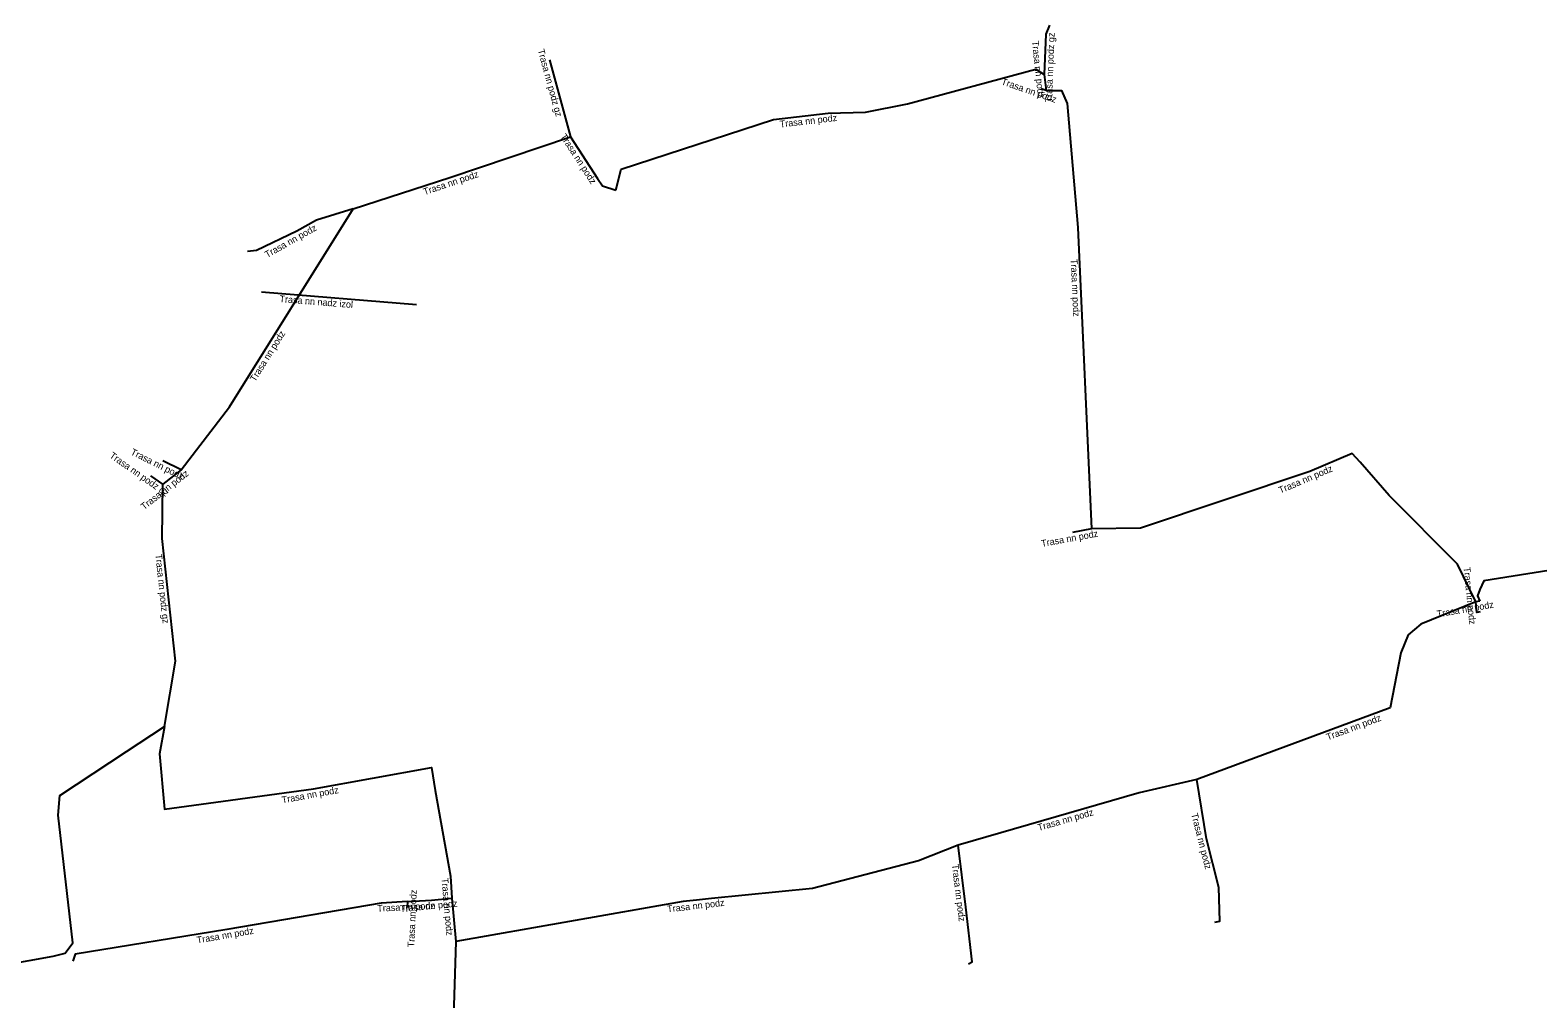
# Model space of a CAD drawing. Extents: x -682739 to -681564, y -1060091 to -1059590.
# Drawn here: x -682114 to -682002.1, y -1059785.7 to -1059713.9 of the extents above; entities that cross this region are included whole.
import ezdxf

# ---------------------------------------------------------------- set-up
doc = ezdxf.new("R2010")
doc.units = 0
doc.layers.add('Popiskový text - Ostatní atributy Trasy', color=7, linetype='Continuous')
doc.layers.add('Spojnice NN', color=7, linetype='Continuous')

msp = doc.modelspace()

# ---------------------------------------------------------------- linework, layer by layer
at = {"layer": 'Spojnice NN'}
for points in [[(-682038.37, -1059713.5), (-682038.63, -1059714.17), (-682038.75, -1059717.15)], [(-682075.45, -1059716.08), (-682073.88, -1059721.78)], [(-682070.52, -1059725.73), (-682070.13, -1059724.17), (-682058.84, -1059720.49), (-682054.79, -1059720.02), (-682052, -1059719.96), (-682048.89, -1059719.33), (-682039.37, -1059716.77), (-682038.75, -1059717.15)], [(-682038.75, -1059717.15), (-682038.62, -1059718.35)], [(-682038.62, -1059718.35), (-682038.97, -1059718.23)], [(-682038.62, -1059718.35), (-682037.46, -1059718.35), (-682037.04, -1059719.3), (-682036.25, -1059728.49), (-682035.24, -1059750.85)], [(-682090.02, -1059727.12), (-682082.85, -1059724.8), (-682073.88, -1059721.78)], [(-682073.88, -1059721.78), (-682071.89, -1059724.86), (-682071.52, -1059725.41), (-682070.52, -1059725.73)], [(-682102.77, -1059746.48), (-682099.19, -1059741.81), (-682090.02, -1059727.12)], [(-682090.02, -1059727.12), (-682092.74, -1059727.97), (-682094.18, -1059728.78), (-682097.18, -1059730.21), (-682097.86, -1059730.28)], [(-682096.81, -1059733.27), (-682085.31, -1059734.2)], [(-682102.77, -1059746.48), (-682104.13, -1059745.8)], [(-682006.74, -1059756.26), (-682008.1, -1059753.47), (-682013.17, -1059748.37), (-682015.33, -1059745.91), (-682015.92, -1059745.26), (-682019.04, -1059746.59), (-682031.61, -1059750.8), (-682035.24, -1059750.85)], [(-682104.12, -1059747.54), (-682105.02, -1059746.91)], [(-682102.77, -1059746.48), (-682104.12, -1059747.54)], [(-682104, -1059765.49), (-682103.18, -1059760.66), (-682104.17, -1059751.56), (-682104.12, -1059747.54)], [(-681973.04, -1059750.26), (-681976.75, -1059750.5), (-681993.23, -1059752.66), (-682006.15, -1059754.71), (-682006.44, -1059755.34), (-682006.62, -1059755.81), (-682006.45, -1059756.21)], [(-682035.24, -1059750.85), (-682036.66, -1059751.11)], [(-682006.74, -1059756.26), (-682010.82, -1059757.92), (-682011.77, -1059758.71), (-682012.3, -1059760.03), (-682013.09, -1059764.13), (-682027.43, -1059769.44)], [(-682006.45, -1059756.21), (-682006.74, -1059756.26)], [(-682006.42, -1059757), (-682006.66, -1059757.05), (-682006.74, -1059756.26)], [(-682117.89, -1059783.54), (-682112.27, -1059782.52), (-682111.38, -1059782.3), (-682110.81, -1059781.54), (-682111.88, -1059772.07), (-682111.76, -1059770.62), (-682106.83, -1059767.35), (-682104, -1059765.49)], [(-682104, -1059765.49), (-682104.38, -1059767.53), (-682104.01, -1059771.64), (-682092.96, -1059770.12), (-682084.2, -1059768.53), (-682083.93, -1059770.24), (-682082.78, -1059776.61), (-682082.68, -1059778.24)], [(-682027.43, -1059769.44), (-682031.72, -1059770.43), (-682045.14, -1059774.29)], [(-682026.11, -1059780.01), (-682025.72, -1059779.93), (-682025.8, -1059777.43), (-682026.72, -1059773.84), (-682027.43, -1059769.44)], [(-682045.14, -1059774.29), (-682048.09, -1059775.45), (-682055.93, -1059777.51), (-682063.42, -1059778.26), (-682064.54, -1059778.39), (-682065.53, -1059778.47), (-682082.4, -1059781.44)], [(-682044.37, -1059783.11), (-682044.09, -1059782.95), (-682044.56, -1059778.91), (-682045.14, -1059774.29)], [(-682085.98, -1059778.48), (-682087.94, -1059778.6), (-682099.39, -1059780.56), (-682110.62, -1059782.39), (-682110.81, -1059782.91)], [(-682085.98, -1059778.48), (-682086, -1059778.93)], [(-682085.98, -1059778.48), (-682084.21, -1059778.39)], [(-682084.21, -1059778.39), (-682082.68, -1059778.24)], [(-682082.68, -1059778.24), (-682082.4, -1059781.44)], [(-682082.4, -1059781.44), (-682082.96, -1059799.69), (-682083.41, -1059815.33), (-682084.2, -1059822.7), (-682084.78, -1059823.76)]]:
    msp.add_lwpolyline(points, dxfattribs=at)

# ---------------------------------------------------------------- texts
at = {"layer": 'Popiskový text - Ostatní atributy Trasy'}
for s, rotation, p in [('Trasa nn podz', 276.1829, (-682039.67, -1059714.69)), ('Trasa nn podz gz', 87.7486, (-682038.18, -1059719.22)), ('Trasa nn podz gz', 285.3996, (-682076.33, -1059715.35)), ('Trasa nn podz', 341.0754, (-682041.98, -1059717.88)), ('Trasa nn podz', 6.6195, (-682058.34, -1059721.09)), ('Trasa nn podz', 302.8667, (-682074.67, -1059721.75)), ('Trasa nn podz', 18.6072, (-682084.71, -1059726.11)), ('Trasa nn podz', 29.3578, (-682096.39, -1059730.77)), ('Trasa nn podz', 272.5863, (-682036.79, -1059730.85)), ('Trasa nn nadz izol', 355.3642, (-682095.49, -1059734.03)), ('Trasa nn podz', 58.0262, (-682097.28, -1059739.98)), ('Trasa nn podz', 333.4349, (-682106.56, -1059745.31)), ('Trasa nn podz gz', 325.008, (-682108.13, -1059745.52)), ('Trasa nn podz', 38.1385, (-682105.52, -1059749.47)), ('Trasa nn podz', 23.0877, (-682021.24, -1059748.24)), ('Trasa nn podz', 10.3758, (-682038.93, -1059752.19)), ('Trasa nn podz gz', 276.2089, (-682104.69, -1059752.75)), ('Trasa nn podz', 275.7824, (-682007.65, -1059753.71)), ('Trasa nn podz', 9.7824, (-682009.59, -1059757.41)), ('Trasa nn podz', 20.3192, (-682017.72, -1059766.54)), ('Trasa nn podz', 10.2876, (-682095.26, -1059771.2)), ('Trasa nn podz', 16.0468, (-682039.16, -1059773.25)), ('Trasa nn podz', 284.3737, (-682027.86, -1059771.99)), ('Trasa nn podz', 277.1555, (-682045.61, -1059775.74)), ('Trasa nn podz', 275.0006, (-682083.46, -1059776.76)), ('Trasa nn podz', 5.5993, (-682086.51, -1059779.27)), ('Trasa nn podz', 87.4552, (-682085.48, -1059781.88)), ('Trasa nn podz', 6.6208, (-682066.69, -1059779.29)), ('Trasa nn podz', 2.9108, (-682088.21, -1059779.24)), ('Trasa nn podz', 9.7137, (-682101.57, -1059781.59))]:
    msp.add_text(s, height=0.5, rotation=rotation, dxfattribs=at).set_placement(p)

doc.saveas('drawing.dxf')
